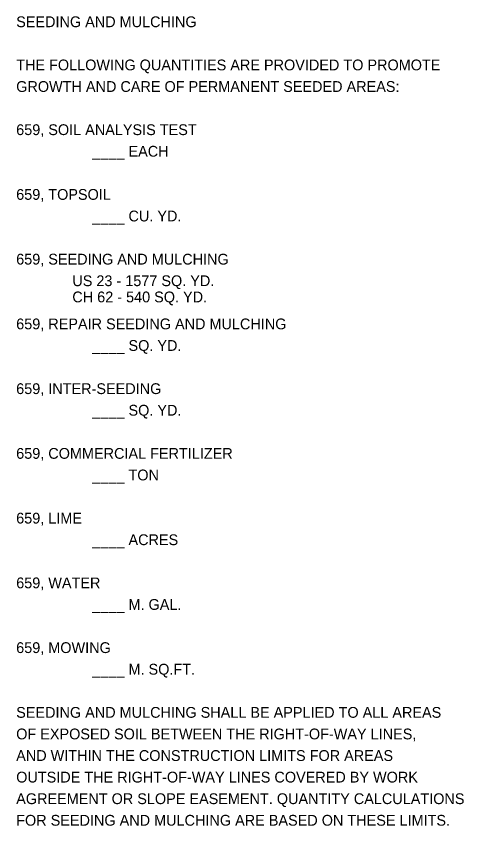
# Model space of a CAD drawing. Extents: x -14.3 to 49.6, y -18.9 to 35.3.
# Drawn here: x 10.66 to 16.47, y 24.76 to 35.27 of the extents above; entities that cross this region are included whole.
import ezdxf

# ---------------------------------------------------------------- set-up
doc = ezdxf.new("R2010")
doc.units = 0
doc.layers.add('SH_Text', color=7, linetype='Continuous')

msp = doc.modelspace()

# ---------------------------------------------------------------- texts
at = {"layer": 'SH_Text'}
for s, p in [('SEEDING AND MULCHING', (10.659, 35.125)), ('THE FOLLOWING QUANTITIES ARE PROVIDED TO PROMOTE', (10.659, 34.565)), ('GROWTH AND CARE OF PERMANENT SEEDED AREAS:', (10.659, 34.285)), ('659, SOIL ANALYSIS TEST', (10.659, 33.725)), ('                   ____ EACH', (10.659, 33.445)), ('659, TOPSOIL', (10.659, 32.885)), ('                   ____ CU. YD.', (10.659, 32.605)), ('659, SEEDING AND MULCHING', (10.659, 32.045)), ('              US 23 - 1577 SQ. YD.', (10.659, 31.765)), ('              CH 62 - 540 SQ. YD.', (10.659, 31.555)), ('659, REPAIR SEEDING AND MULCHING', (10.659, 31.205)), ('                   ____ SQ. YD.', (10.659, 30.925)), ('659, INTER-SEEDING', (10.659, 30.365)), ('                   ____ SQ. YD.', (10.659, 30.085)), ('659, COMMERCIAL FERTILIZER', (10.659, 29.525)), ('                   ____ TON', (10.659, 29.245)), ('659, LIME', (10.659, 28.685)), ('                   ____ ACRES', (10.659, 28.405)), ('659, WATER', (10.659, 27.845)), ('                   ____ M. GAL.', (10.659, 27.565)), ('659, MOWING', (10.659, 27.005)), ('                   ____ M. SQ.FT.', (10.659, 26.725)), ('SEEDING AND MULCHING SHALL BE APPLIED TO ALL AREAS', (10.659, 26.165)), ('OF EXPOSED SOIL BETWEEN THE RIGHT-OF-WAY LINES,', (10.659, 25.885)), ('AND WITHIN THE CONSTRUCTION LIMITS FOR AREAS', (10.659, 25.605)), ('OUTSIDE THE RIGHT-OF-WAY LINES COVERED BY WORK', (10.659, 25.325)), ('AGREEMENT OR SLOPE EASEMENT. QUANTITY CALCULATIONS', (10.659, 25.045)), ('FOR SEEDING AND MULCHING ARE BASED ON THESE LIMITS.', (10.659, 24.765))]:
    msp.add_text(s, height=0.14, dxfattribs=at).set_placement(p)

doc.saveas('drawing.dxf')
